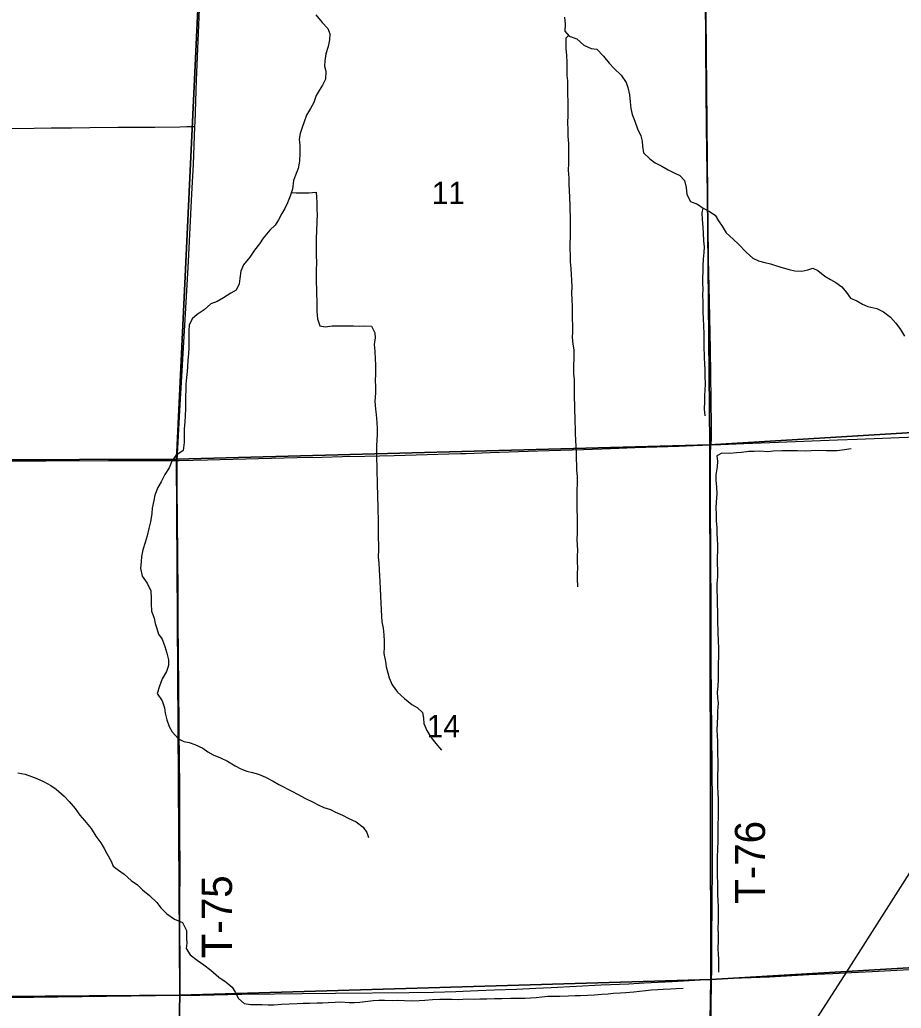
# Model space of a CAD drawing. Extents: x -8.5 to 18.7, y -20.3 to 7.
# Drawn here: x -5.484 to -2.162, y -16.948 to -13.223 of the extents above; entities that cross this region are included whole.
import ezdxf

# ---------------------------------------------------------------- set-up
doc = ezdxf.new("R2010")
doc.units = 0
for name, color, linetype in [('GM_X_County_Road', 7, 'Continuous'), ('GM_X_Minor_River', 7, 'Continuous'), ('GM_X_Rail_Line', 7, 'Continuous'), ('GM_X_Section', 7, 'Continuous'), ('GM_X_Section_Text', 7, 'Continuous'), ('GM_X_Township_Road', 7, 'Continuous'), ('GM_X_Township_Road_Text', 7, 'Continuous')]:
    doc.layers.add(name, color=color, linetype=linetype)

msp = doc.modelspace()

# ---------------------------------------------------------------- linework, layer by layer
at = {"layer": 'GM_X_County_Road'}
for points in [[(-2.8768, -16.8387), (-2.8636, -16.838), (-2.7966, -16.8348), (-2.6587, -16.8288), (-2.5109, -16.8208), (-2.4202, -16.8168), (-2.3494, -16.8128), (-2.2724, -16.8089), (-2.1309, -16.8011)], [(-4.8799, -16.8985), (-4.8047, -16.8978), (-4.6468, -16.895), (-4.5237, -16.8937), (-4.4193, -16.892), (-4.2937, -16.8905), (-4.0164, -16.8882), (-3.9244, -16.8867), (-3.8411, -16.8841), (-3.7579, -16.8804), (-3.6958, -16.8781), (-3.6121, -16.8753), (-3.5393, -16.8723), (-3.4808, -16.8692), (-3.2933, -16.86), (-3.189, -16.8553), (-3.1306, -16.8524), (-3.025, -16.8469), (-2.9617, -16.8434), (-2.8768, -16.8387)], [(-5.9046, -16.903), (-5.8878, -16.903), (-5.8679, -16.9028), (-5.802, -16.9024), (-5.6652, -16.902), (-5.3879, -16.9005), (-5.2225, -16.8994), (-5.1318, -16.8991), (-5.0323, -16.8988), (-4.9278, -16.8989), (-4.8799, -16.8985)]]:
    msp.add_lwpolyline(points, dxfattribs=at)
at = {"layer": 'GM_X_Minor_River'}
for points in [[(-4.3675, -13.205), (-4.3442, -13.234), (-4.3224, -13.2568), (-4.3157, -13.2766), (-4.3166, -13.2986), (-4.3213, -13.3244), (-4.3298, -13.3524), (-4.3345, -13.3781), (-4.3353, -13.3979), (-4.3309, -13.4169), (-4.3318, -13.4472), (-4.3433, -13.4699), (-4.3555, -13.4895), (-4.367, -13.5092), (-4.3762, -13.5349), (-4.3885, -13.5576), (-4.403, -13.5826), (-4.4122, -13.6083), (-4.4192, -13.6295), (-4.4269, -13.6515), (-4.4315, -13.6734), (-4.4286, -13.6954), (-4.428, -13.7265), (-4.429, -13.7561), (-4.4344, -13.7834), (-4.4452, -13.8091), (-4.4521, -13.8296), (-4.4561, -13.8622), (-4.4645, -13.8879), (-4.4753, -13.9136)], [(-3.4315, -13.214), (-3.4287, -13.2398), (-3.4296, -13.2664), (-3.413, -13.2854), (-3.3851, -13.2955), (-3.358, -13.3191), (-3.3301, -13.3314), (-3.3097, -13.3338), (-3.2848, -13.3605), (-3.2623, -13.3864)], [(-3.4156, -13.2825), (-3.4267, -13.2929), (-3.4261, -13.3127), (-3.4262, -13.3332), (-3.4241, -13.3574), (-3.4227, -13.3848), (-3.4228, -13.4067), (-3.4222, -13.4333), (-3.4201, -13.453), (-3.4195, -13.4857), (-3.4196, -13.5046), (-3.419, -13.5297), (-3.4192, -13.563), (-3.4185, -13.5828), (-3.4195, -13.6123), (-3.4189, -13.6374), (-3.4182, -13.6616), (-3.4161, -13.6897), (-3.4155, -13.7155), (-3.4157, -13.739), (-3.4166, -13.7648), (-3.4167, -13.7898), (-3.4154, -13.8202), (-3.4148, -13.8445), (-3.4141, -13.8657), (-3.4128, -13.8945), (-3.4107, -13.9234), (-3.4108, -13.9423), (-3.4094, -13.9636), (-3.4096, -13.9894), (-3.4097, -14.0137), (-3.4099, -14.0425), (-3.4108, -14.0667), (-3.4109, -14.088), (-3.4103, -14.11), (-3.4096, -14.135), (-3.4075, -14.1608), (-3.4061, -14.1843), (-3.4047, -14.2041), (-3.4034, -14.2314), (-3.4043, -14.2519), (-3.4037, -14.2792), (-3.4023, -14.3034), (-3.4026, -14.3512), (-3.4004, -14.374), (-3.4006, -14.3998), (-3.4022, -14.421), (-3.4001, -14.4446), (-3.3957, -14.4681), (-3.3966, -14.4977), (-3.3976, -14.5288), (-3.397, -14.5591), (-3.3948, -14.5781), (-3.3942, -14.6031), (-3.3945, -14.6471), (-3.3939, -14.6752), (-3.3932, -14.6972), (-3.3926, -14.7207), (-3.392, -14.7397), (-3.3913, -14.7624), (-3.3907, -14.7829), (-3.3893, -14.8057), (-3.3887, -14.8322), (-3.3874, -14.858), (-3.3867, -14.8808), (-3.3861, -14.8997), (-3.3854, -14.9195), (-3.3833, -14.946), (-3.3835, -14.9718), (-3.3844, -14.9946), (-3.3847, -15.0484), (-3.3841, -15.0712), (-3.3834, -15.0955), (-3.3838, -15.1577), (-3.3847, -15.1819), (-3.3833, -15.2024), (-3.3827, -15.2214), (-3.3835, -15.2441), (-3.3837, -15.2661), (-3.3823, -15.2881), (-3.3839, -15.3094), (-3.3833, -15.3291), (-3.3819, -15.3602)], [(-3.2623, -13.3864), (-3.2435, -13.407), (-3.2179, -13.4322), (-3.1992, -13.4596), (-3.1924, -13.4786), (-3.1866, -13.5067), (-3.1837, -13.5325), (-3.1816, -13.5575), (-3.1764, -13.5803), (-3.1667, -13.6054), (-3.1563, -13.6343), (-3.1436, -13.6609), (-3.1391, -13.6806), (-3.137, -13.6996), (-3.1341, -13.7254), (-3.1093, -13.7476), (-3.0897, -13.7628), (-3.0648, -13.7751), (-3.0406, -13.7889), (-3.0157, -13.8012), (-2.9961, -13.8096), (-2.9788, -13.8295), (-2.9729, -13.856), (-2.9708, -13.8818), (-2.9558, -13.9077), (-2.9294, -13.9177), (-2.9083, -13.9338), (-2.8842, -13.9453), (-2.8638, -13.9591), (-2.8511, -13.9804), (-2.8368, -14.0017), (-2.8226, -14.026), (-2.7955, -14.0497), (-2.7752, -14.0688), (-2.7466, -14.0993), (-2.721, -14.1222), (-2.6999, -14.1314), (-2.6757, -14.1376), (-2.6553, -14.143), (-2.6356, -14.1492), (-2.6069, -14.1585), (-2.5843, -14.1647), (-2.5639, -14.1693), (-2.5366, -14.1702), (-2.5147, -14.1651), (-2.4957, -14.1598), (-2.4761, -14.1675), (-2.4505, -14.1897), (-2.4286, -14.2019), (-2.409, -14.2134), (-2.3864, -14.2302), (-2.3691, -14.2516), (-2.3534, -14.2722), (-2.33, -14.2829), (-2.3088, -14.2952), (-2.2877, -14.3036), (-2.2545, -14.3114), (-2.2288, -14.3237), (-2.2032, -14.3443), (-2.1821, -14.3664), (-2.1656, -14.3908), (-2.1499, -14.4151)], [(-4.4602, -13.8746), (-4.4418, -13.8759), (-4.4206, -13.876), (-4.3941, -13.8754), (-4.3669, -13.8733), (-4.3654, -13.8923), (-4.364, -13.912), (-4.3642, -13.937), (-4.3636, -13.9598), (-4.3637, -13.981), (-4.3654, -14.022), (-4.3663, -14.0432), (-4.3664, -14.0622), (-4.3673, -14.0842), (-4.3667, -14.1122), (-4.3661, -14.138), (-4.367, -14.1676), (-4.3672, -14.1919), (-4.3665, -14.2131), (-4.3659, -14.2374), (-4.3653, -14.2586), (-4.3647, -14.2806), (-4.364, -14.3004), (-4.3642, -14.3224), (-4.3621, -14.3504), (-4.3524, -14.3763), (-4.3327, -14.3802), (-4.3062, -14.3765), (-4.2782, -14.3767), (-4.2479, -14.3769), (-4.226, -14.3762), (-4.2025, -14.3779), (-4.1829, -14.3765), (-4.1587, -14.3774), (-4.1452, -14.4025), (-4.1445, -14.4222), (-4.1477, -14.4464), (-4.1456, -14.4722), (-4.1442, -14.5018), (-4.1436, -14.5223), (-4.1438, -14.561), (-4.1447, -14.58), (-4.1433, -14.6073), (-4.1435, -14.6293), (-4.1452, -14.6611), (-4.1431, -14.6907), (-4.1409, -14.7104), (-4.1381, -14.7408), (-4.1367, -14.7628), (-4.1376, -14.7848), (-4.1385, -14.8091), (-4.1393, -14.828), (-4.1394, -14.8485), (-4.1389, -14.8789), (-4.1383, -14.9039), (-4.1384, -14.9297), (-4.1371, -14.9615), (-4.1365, -14.9851), (-4.1358, -15.004), (-4.1352, -15.0291), (-4.1345, -15.048), (-4.1339, -15.0731), (-4.1326, -15.1034), (-4.1335, -15.1231), (-4.1336, -15.1535), (-4.133, -15.1747), (-4.1317, -15.2013), (-4.1318, -15.221), (-4.1327, -15.2483), (-4.1313, -15.2703), (-4.1299, -15.2961), (-4.1285, -15.3173), (-4.1272, -15.3401), (-4.1258, -15.3674), (-4.1231, -15.422), (-4.1225, -15.4448), (-4.1211, -15.4721), (-4.1197, -15.4919), (-4.1146, -15.5162), (-4.1124, -15.5404), (-4.1111, -15.5647), (-4.1104, -15.586), (-4.1113, -15.6117), (-4.1062, -15.6414), (-4.1033, -15.6619), (-4.0974, -15.6839), (-4.0914, -15.7029), (-4.081, -15.7287), (-4.06, -15.7569), (-4.0336, -15.7806), (-4.0058, -15.8035), (-3.9861, -15.8142), (-3.9666, -15.834), (-3.9622, -15.8553), (-3.9608, -15.8743), (-3.9503, -15.9016), (-3.9353, -15.9268), (-3.9158, -15.9504), (-3.894, -15.9748)], [(-4.4753, -13.9136), (-4.4852, -13.9341), (-4.496, -13.9537), (-4.509, -13.9772), (-4.5219, -13.9968), (-4.5417, -14.0157), (-4.5661, -14.0466), (-4.5798, -14.0678), (-4.5989, -14.0912), (-4.6172, -14.1177), (-4.6401, -14.1471), (-4.6501, -14.1706), (-4.654, -14.1979), (-4.6564, -14.2183), (-4.6679, -14.2425), (-4.6884, -14.253), (-4.7157, -14.2711), (-4.7393, -14.2846), (-4.7635, -14.2943), (-4.7886, -14.3169), (-4.8152, -14.3342), (-4.8342, -14.3501), (-4.8457, -14.3735), (-4.8466, -14.3948), (-4.8467, -14.4175), (-4.8461, -14.4365), (-4.847, -14.46), (-4.8478, -14.4805), (-4.8503, -14.507), (-4.8519, -14.5297), (-4.8528, -14.5487), (-4.8552, -14.5707), (-4.8576, -14.5965), (-4.8577, -14.6192), (-4.8594, -14.6397), (-4.8587, -14.6632), (-4.8589, -14.6882), (-4.8598, -14.7163), (-4.8614, -14.7383), (-4.8639, -14.7656), (-4.8642, -14.8156), (-4.8674, -14.846), (-4.8962, -14.8655), (-4.9107, -14.8867), (-4.9207, -14.9117), (-4.9375, -14.9366), (-4.9513, -14.9646), (-4.9628, -14.9858), (-4.975, -15.0145), (-4.9789, -15.0342), (-4.9852, -15.0638), (-4.986, -15.0842), (-4.9907, -15.1146), (-4.9969, -15.1403), (-5.0032, -15.1683), (-5.0109, -15.1926), (-5.0194, -15.2206), (-5.0248, -15.2456), (-5.0264, -15.2653), (-5.0281, -15.2896), (-5.0222, -15.3199), (-5.0034, -15.3458), (-4.99, -15.3747), (-4.9879, -15.4043), (-4.988, -15.424), (-4.9874, -15.4514), (-4.9777, -15.478), (-4.974, -15.4977), (-4.9674, -15.5175), (-4.9607, -15.538), (-4.9472, -15.557), (-4.9375, -15.5851), (-4.9301, -15.6102), (-4.9234, -15.6345), (-4.9228, -15.6565), (-4.9305, -15.6792), (-4.9465, -15.7064), (-4.9565, -15.7345), (-4.9657, -15.7617), (-4.9477, -15.7891), (-4.9381, -15.8157), (-4.9359, -15.8362), (-4.9292, -15.8605), (-4.9211, -15.8864), (-4.9098, -15.9061), (-4.885, -15.9321), (-4.8654, -15.9428), (-4.845, -15.9467), (-4.8238, -15.9544), (-4.7944, -15.9675), (-4.7748, -15.9812), (-4.7552, -15.9927), (-4.7273, -16.0043), (-4.7009, -16.0173), (-4.6715, -16.0341), (-4.6503, -16.0456), (-4.6284, -16.0541), (-4.6073, -16.0595), (-4.5846, -16.0657), (-4.5582, -16.0773), (-4.5288, -16.0918)], [(-2.9096, -13.9328), (-2.9137, -13.9512), (-2.9123, -13.9762), (-2.9102, -14.0051), (-2.9089, -14.0278), (-2.9075, -14.0559), (-2.9054, -14.0794), (-2.9062, -14.0999), (-2.9087, -14.1257), (-2.9096, -14.1515), (-2.9097, -14.1719), (-2.9106, -14.1962), (-2.9107, -14.2152), (-2.9101, -14.2402), (-2.911, -14.2592), (-2.9104, -14.2872), (-2.9097, -14.3062), (-2.9098, -14.3259), (-2.9092, -14.3472), (-2.9079, -14.3775), (-2.9065, -14.4056), (-2.9059, -14.4291), (-2.906, -14.4496), (-2.9048, -14.4966), (-2.9034, -14.5194), (-2.9028, -14.5414), (-2.9021, -14.5664), (-2.9008, -14.5968), (-2.9025, -14.6195), (-2.9033, -14.6392), (-2.9042, -14.6635), (-2.9051, -14.6893), (-2.903, -14.7158)], [(-2.3506, -14.8403), (-2.3763, -14.844), (-2.4036, -14.8476), (-2.4445, -14.8474), (-2.4725, -14.8464), (-2.5012, -14.8478), (-2.5247, -14.8484), (-2.5534, -14.8475), (-2.5799, -14.8481), (-2.6117, -14.8479), (-2.645, -14.8485), (-2.6654, -14.8507), (-2.6964, -14.849), (-2.7169, -14.8496), (-2.7366, -14.8503), (-2.7638, -14.8532), (-2.7835, -14.8546), (-2.81, -14.8575), (-2.8388, -14.8565), (-2.8577, -14.8663), (-2.8541, -14.886), (-2.8565, -14.908), (-2.8604, -14.9383), (-2.8605, -14.9581), (-2.8584, -14.9839), (-2.857, -15.0089), (-2.8603, -15.0415), (-2.8604, -15.0627), (-2.8598, -15.087), (-2.8592, -15.1113), (-2.8578, -15.1371), (-2.8572, -15.1598), (-2.8558, -15.1796), (-2.8551, -15.2023), (-2.8545, -15.2236), (-2.8562, -15.2494), (-2.8563, -15.2751), (-2.8549, -15.2956), (-2.8551, -15.3222), (-2.8567, -15.348), (-2.8569, -15.3715), (-2.8555, -15.4011), (-2.8557, -15.4261), (-2.8551, -15.4511), (-2.8545, -15.4822), (-2.8533, -15.5369), (-2.8527, -15.5589), (-2.8514, -15.596), (-2.8508, -15.6256), (-2.8517, -15.6461), (-2.8525, -15.665), (-2.8527, -15.6886), (-2.852, -15.7075), (-2.8537, -15.7348), (-2.8553, -15.7568), (-2.8547, -15.7781), (-2.8525, -15.7985), (-2.8542, -15.8289), (-2.8544, -15.8486), (-2.8553, -15.8744), (-2.8569, -15.8986), (-2.8555, -15.9214), (-2.8549, -15.9419), (-2.8551, -15.9707), (-2.8544, -15.9897), (-2.8531, -16.017), (-2.854, -16.0428), (-2.8549, -16.0693), (-2.855, -16.0906), (-2.8544, -16.111), (-2.853, -16.1384), (-2.8516, -16.1604), (-2.8525, -16.1816), (-2.8526, -16.2044), (-2.852, -16.2309), (-2.8529, -16.2514), (-2.8531, -16.2772), (-2.854, -16.2999), (-2.8533, -16.3204), (-2.8542, -16.3462), (-2.8559, -16.3811), (-2.8563, -16.4486), (-2.855, -16.4759), (-2.8543, -16.4971), (-2.8545, -16.5176), (-2.8539, -16.5442), (-2.8525, -16.5646), (-2.8519, -16.5942), (-2.852, -16.6223), (-2.8529, -16.645), (-2.8523, -16.6708), (-2.8517, -16.6928), (-2.8534, -16.7239), (-2.852, -16.7437), (-2.8514, -16.7626), (-2.8508, -16.7922), (-2.8509, -16.8119)], [(-5.4903, -16.0607), (-5.4639, -16.0661), (-5.439, -16.0746), (-5.4193, -16.0816), (-5.3937, -16.0938), (-5.3665, -16.1084), (-5.3469, -16.1222), (-5.3168, -16.1489), (-5.2973, -16.1687), (-5.2755, -16.1946), (-5.2575, -16.2197), (-5.2394, -16.2403), (-5.2146, -16.2701), (-5.1966, -16.299), (-5.1779, -16.3249), (-5.1651, -16.3462), (-5.1561, -16.3652), (-5.1397, -16.3933), (-5.1322, -16.4124), (-5.1111, -16.4269), (-5.09, -16.4422), (-5.0637, -16.4658), (-5.0395, -16.4827), (-5.0207, -16.5017), (-4.9951, -16.5223), (-4.9673, -16.549), (-4.9523, -16.5696), (-4.9297, -16.5917), (-4.9011, -16.6124), (-4.8709, -16.6247), (-4.8559, -16.6551), (-4.8553, -16.6832), (-4.8547, -16.7029), (-4.8563, -16.7226), (-4.8413, -16.7462), (-4.8149, -16.7668), (-4.7901, -16.7844), (-4.7637, -16.8043), (-4.7336, -16.831), (-4.7057, -16.8494), (-4.6839, -16.8684), (-4.6719, -16.8875), (-4.6592, -16.9111), (-4.6381, -16.9301), (-4.6146, -16.9333), (-4.5904, -16.9334), (-4.57, -16.9335), (-4.5481, -16.9344), (-4.5261, -16.9346), (-4.4974, -16.9324), (-4.4686, -16.9311), (-4.4383, -16.9297), (-4.4164, -16.9291), (-4.3922, -16.9285), (-4.3634, -16.9271), (-4.343, -16.9272), (-4.3218, -16.9266), (-4.2953, -16.9252), (-4.2733, -16.9238), (-4.2423, -16.9255), (-4.2219, -16.9256), (-4.2022, -16.9242), (-4.1818, -16.9221), (-4.1522, -16.9184), (-4.131, -16.917), (-4.1091, -16.9172), (-4.0803, -16.9181), (-4.0591, -16.9174), (-4.0342, -16.9183), (-4.0077, -16.92), (-3.9789, -16.9186), (-3.9578, -16.9172)], [(-4.5288, -16.0918), (-4.5077, -16.1048), (-4.4579, -16.1302), (-4.4352, -16.1424), (-4.4096, -16.1562), (-4.3787, -16.1708), (-4.3591, -16.1815), (-4.3379, -16.1907), (-4.313, -16.1992), (-4.2934, -16.2092), (-4.267, -16.2207), (-4.2436, -16.2322), (-4.2164, -16.2453), (-4.1893, -16.2652), (-4.1765, -16.2849), (-4.1698, -16.3039)], [(-3.9578, -16.9172), (-3.9282, -16.9151), (-3.901, -16.9138), (-3.8768, -16.9131), (-3.8541, -16.9133), (-3.8306, -16.9142), (-3.7973, -16.9128), (-3.7708, -16.913), (-3.7496, -16.9123), (-3.7232, -16.9125), (-3.6944, -16.9111), (-3.6672, -16.9105), (-3.6339, -16.9092), (-3.5809, -16.9095), (-3.5589, -16.9088), (-3.5385, -16.9067), (-3.5165, -16.9045), (-3.4938, -16.9024), (-3.4726, -16.9017), (-3.4492, -16.9019), (-3.4174, -16.9013), (-3.3909, -16.8999), (-3.3712, -16.8993), (-3.344, -16.8987), (-3.3175, -16.8965), (-3.2902, -16.8944), (-3.2668, -16.893), (-3.2471, -16.8909), (-3.2198, -16.8895), (-3.2002, -16.8881), (-3.1699, -16.8852), (-3.1487, -16.8831), (-3.1252, -16.8809), (-3.104, -16.8788), (-3.079, -16.8774), (-3.0593, -16.876), (-3.0321, -16.8739), (-3.0101, -16.8732), (-2.9844, -16.8726)]]:
    msp.add_lwpolyline(points, dxfattribs=at)
at = {"layer": 'GM_X_Rail_Line'}
msp.add_lwpolyline([(-4.5197, -20.262), (-4.302, -19.9023), (-3.8337, -19.1615), (-3.3722, -18.402), (-3.0035, -17.8228), (-2.5461, -17.0881), (-2.3673, -16.8107), (-1.6987, -15.76), (-1.0634, -14.7163), (-0.8647, -14.409), (-0.5398, -13.878), (-0.1554, -13.2519), (0.2117, -12.6573), (0.7735, -11.7893), (0.878, -11.6305)], dxfattribs=at)
at = {"layer": 'GM_X_Section'}
for points in [[(-2.9026, -12.8057), (-0.8312, -12.6964), (-0.8797, -14.6721), (-0.8807, -14.7032), (-2.8839, -14.825)], [(-4.7978, -12.8645), (-2.9026, -12.8057), (-2.8839, -14.825), (-4.8936, -14.8786)], [(-6.8207, -12.8849), (-4.7978, -12.8645), (-4.8936, -14.8786), (-6.7244, -14.8856), (-6.7617, -14.836), (-6.7767, -14.8143), (-6.7888, -14.7956)], [(-2.8839, -14.825), (-0.8807, -14.7032), (-0.9212, -16.7237), (-2.8804, -16.8389)], [(-4.8936, -14.8786), (-2.8839, -14.825), (-2.8804, -16.8389), (-4.8803, -16.8978)], [(-6.7244, -14.8856), (-4.8936, -14.8786), (-4.8803, -16.8978), (-6.8119, -16.9248), (-6.8038, -16.7539), (-6.8038, -16.6803), (-6.7989, -16.5969), (-6.7842, -16.5429), (-6.7645, -16.4595), (-6.7645, -16.3957), (-6.7694, -16.2584), (-6.7694, -16.1701), (-6.7891, -16.067), (-6.8332, -15.8414), (-6.8479, -15.7629), (-6.8479, -15.6991), (-6.7792, -15.5715), (-6.686, -15.3998), (-6.637, -15.287), (-6.6174, -15.1644), (-6.637, -15.0711), (-6.6615, -14.9926), (-6.682, -14.9465), (-6.6958, -14.9142)], [(-0.9212, -16.7237), (-0.9213, -16.7479), (-0.9282, -18.7246), (-2.9125, -18.848), (-2.8804, -16.8389)], [(-4.8803, -16.8978), (-2.8804, -16.8389), (-2.9125, -18.848), (-4.9245, -18.9152)], [(-6.8119, -16.9248), (-4.8803, -16.8978), (-4.9245, -18.9152), (-6.9481, -18.8937), (-6.9297, -17.5727), (-6.9291, -17.4939), (-6.8886, -17.439), (-6.873, -17.4115), (-6.8551, -17.3757), (-6.8396, -17.3316), (-6.8241, -17.291), (-6.8062, -17.2385), (-6.8002, -17.2051), (-6.7931, -17.1728), (-6.7919, -17.1335), (-6.7907, -17.1036), (-6.7943, -17.0714), (-6.7971, -17.0342), (-6.7978, -17.0237), (-6.8026, -16.9986), (-6.8098, -16.9592)]]:
    msp.add_lwpolyline(points, close=True, dxfattribs=at)
at = {"layer": 'GM_X_Township_Road'}
for points in [[(-2.8788, -14.8248), (-2.8782, -14.8161), (-2.8776, -14.8084), (-2.8771, -14.7959), (-2.8773, -14.7523), (-2.8786, -14.6566), (-2.8813, -14.4651), (-2.8853, -14.2836), (-2.8883, -14.1246), (-2.8901, -13.9965), (-2.8919, -13.8933), (-2.8939, -13.7877), (-2.8943, -13.7268), (-2.8972, -13.5018), (-2.8988, -13.3103), (-2.9, -13.135), (-2.9019, -12.9373), (-2.9027, -12.8739), (-2.9033, -12.8341), (-2.9024, -12.811)], [(-4.8234, -13.6252), (-4.8227, -13.6102), (-4.8175, -13.4511), (-4.8093, -13.2437), (-4.799, -12.999), (-4.7948, -12.8808), (-4.7952, -12.8663)], [(-5.5239, -13.6327), (-5.4295, -13.6322), (-5.3648, -13.6312), (-5.289, -13.6301), (-5.2194, -13.6293), (-5.1126, -13.6286), (-4.9749, -13.6277), (-4.8803, -13.6263), (-4.8547, -13.6258), (-4.8304, -13.6253), (-4.8234, -13.6252)], [(-4.8905, -14.8838), (-4.8806, -14.6955), (-4.8589, -14.3316), (-4.8479, -14.1342), (-4.8351, -13.8797), (-4.8296, -13.7692), (-4.8234, -13.6252)], [(-2.8788, -14.8248), (-2.8416, -14.8233), (-2.7559, -14.8201), (-2.6242, -14.8145), (-2.403, -14.8057), (-2.3285, -14.8031), (-2.1061, -14.7942), (-2.0415, -14.7913), (-1.9707, -14.7876), (-1.9099, -14.784), (-1.8491, -14.7804), (-1.7859, -14.7754), (-1.6806, -14.7667), (-1.4006, -14.7435), (-1.2779, -14.7335), (-1.1527, -14.7236), (-1.0535, -14.7163), (-0.9419, -14.7084), (-0.8781, -14.703)], [(-4.8905, -14.8838), (-4.8835, -14.8838), (-4.7766, -14.8817), (-4.5839, -14.8767), (-4.4385, -14.8732), (-4.344, -14.8709), (-4.267, -14.8689), (-4.1837, -14.8671), (-4.0731, -14.8645), (-3.9488, -14.8614), (-3.8667, -14.8587), (-3.822, -14.8578), (-3.8021, -14.857), (-3.7114, -14.8539), (-3.6046, -14.8497), (-3.5312, -14.8474), (-3.3597, -14.8419), (-3.2566, -14.8382), (-3.1659, -14.8353), (-3.0006, -14.8297), (-2.9435, -14.8274), (-2.8788, -14.8248)], [(-2.8768, -16.8387), (-2.8766, -16.8099), (-2.8754, -16.688), (-2.8738, -16.4158), (-2.8732, -16.1758), (-2.8762, -15.911), (-2.8773, -15.773), (-2.878, -15.6436), (-2.879, -15.4174), (-2.8797, -15.2732), (-2.8808, -15.0046), (-2.8808, -14.9012), (-2.8808, -14.8647), (-2.8808, -14.8489), (-2.8801, -14.8383), (-2.8795, -14.8305), (-2.8788, -14.8248)], [(-6.6054, -14.8878), (-6.592, -14.8878), (-6.5435, -14.8877), (-6.4825, -14.8874), (-6.3346, -14.887), (-6.1356, -14.887), (-5.8211, -14.8862), (-5.6432, -14.8852), (-5.5749, -14.8856), (-5.3859, -14.8851), (-5.1496, -14.8844), (-5.0514, -14.8845), (-4.8905, -14.8838)], [(-4.8799, -16.8985), (-4.8798, -16.892), (-4.8796, -16.8657), (-4.8802, -16.5586), (-4.8797, -16.4218), (-4.8804, -16.2851), (-4.881, -16.1011), (-4.8817, -16.0215), (-4.8831, -15.8923), (-4.8843, -15.7344), (-4.8857, -15.6163), (-4.8865, -15.4944), (-4.8872, -15.3825), (-4.8894, -15.1053), (-4.8902, -14.9896), (-4.8909, -14.925), (-4.8905, -14.8838)], [(-2.9094, -18.8467), (-2.9091, -18.8348), (-2.9071, -18.6769), (-2.9062, -18.5999), (-2.9047, -18.4643), (-2.9031, -18.3549), (-2.902, -18.2791), (-2.9007, -18.1396), (-2.8997, -18.0305), (-2.8965, -17.8652), (-2.8942, -17.7733), (-2.8922, -17.6913), (-2.8898, -17.5744), (-2.8875, -17.4663), (-2.8851, -17.327), (-2.8835, -17.2375), (-2.8804, -17.0772), (-2.878, -16.9305), (-2.8769, -16.8596), (-2.8768, -16.8387)]]:
    msp.add_lwpolyline(points, dxfattribs=at)

# ---------------------------------------------------------------- texts
at = {"layer": 'GM_X_Section_Text'}
for s, p in [('11', (-3.931, -13.9176)), ('14', (-3.9502, -15.927))]:
    msp.add_text(s, height=0.08371, rotation=0, dxfattribs=at).set_placement(p)
at = {"layer": 'GM_X_Township_Road_Text'}
for s, p in [('T-76', (-2.6754, -16.5544)), ('T-75', (-4.684, -16.7594))]:
    msp.add_text(s, height=0.11364, rotation=90, dxfattribs=at).set_placement(p)

doc.saveas('drawing.dxf')
